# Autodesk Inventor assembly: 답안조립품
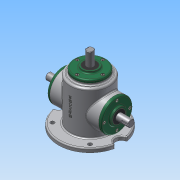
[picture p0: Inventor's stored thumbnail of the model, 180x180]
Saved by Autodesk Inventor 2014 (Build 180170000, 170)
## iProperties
Created: 2018-04
Part Number: 답안조립품
Document SubType Name: Assembly
Designer: user
Author: user
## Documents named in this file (16)
- C:\Users\user\Desktop\480407V1032\답안조립품.iam
- C:\Users\user\Desktop\480407V1032\본체.ipt
- C:\Users\user\Desktop\480407V1032\커버.ipt
- C:\Users\user\Desktop\480407V1032\볼트 M4.ipt
- 볼트 M4.ipt
- C:\Users\user\Desktop\480407V1032\오일 실.ipt
- 오일 실.ipt
- C:\Users\user\Desktop\480407V1032\베어링 6203.ipt
- C:\Users\user\Desktop\480407V1032\서브 축.ipt
- 서브 축.ipt
- C:\Users\user\Desktop\480407V1032\메인 축.ipt
- 메인 축.ipt
- C:\Users\user\Desktop\480407V1032\키 5x5.ipt
- C:\Users\user\Desktop\480407V1032\키 4x4.ipt
- C:\Users\user\Desktop\480407V1032\메인 베벨기어.ipt
- C:\Users\user\Desktop\480407V1032\서브 베벨기어.ipt
